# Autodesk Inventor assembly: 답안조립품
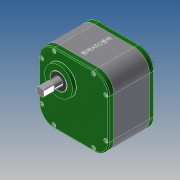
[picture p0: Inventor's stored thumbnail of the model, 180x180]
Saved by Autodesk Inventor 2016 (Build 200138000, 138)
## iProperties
Created: 2017-11
Part Number: 답안조립품
Document SubType Name: Assembly
Designer: Administrator
Mass: 3103.18 g
Surface Area: 2353.72 cm^2
Volume: 855.505 cm^3
Density: 3.6273 g/cm^3
Author: Administrator
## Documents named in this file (11)
- D:\371107V1020장석현\답안조립품.iam
- D:\371107V1020장석현\뒤커버.ipt
- D:\371107V1020장석현\메인축.ipt
- D:\371107V1020장석현\베어링 608.ipt
- D:\371107V1020장석현\베어링 6003.ipt
- D:\371107V1020장석현\본체.ipt
- D:\371107V1020장석현\볼트 M4.ipt
- D:\371107V1020장석현\서브축.ipt
- D:\371107V1020장석현\앞커버.ipt
- D:\371107V1020장석현\오일실 8 22 7.ipt
- D:\371107V1020장석현\오일실 17 32 8.ipt
## Named parameters: d19_d7 = 0, d20_d8 = 0, d21_d9 = 0, d22_d10 = 0
